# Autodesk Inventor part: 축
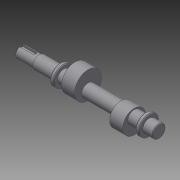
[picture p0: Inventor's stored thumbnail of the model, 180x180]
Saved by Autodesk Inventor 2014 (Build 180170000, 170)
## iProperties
Created: 2014-12
Part Number: 축
Material: 일반
Document SubType Name: Modeling
Designer: Owner
Density: 1 g/cm^3
Appearance: 기본값
Author: Owner
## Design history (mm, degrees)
sketch "스케치1"
  geometry: L1 (-90, 0)-(90, 0); L2 (-90, 0)-(-90, 7.5); L3 (-90, 7.5)-(-66, 7.5); L4 (-66, 7.5)-(-66, 8.5); L5 (-66, 8.5)-(-39, 8.5); L6 (-39, 8.5)-(-39, 13); L7 (-39, 13)-(-34, 13); L8 (-34, 13)-(-34, 8.5); L9 (-34, 8.5)-(72, 8.5); L10 (72, 13)-(72, 8.5); L11 (72, 13)-(77, 13); L12 (77, 13)-(77, 8.5); L13 (77, 8.5)-(90, 8.5); L14 (90, 8.5)-(90, 0); 2 further points
  constraints: 28 end point, 7 parallel, 6 perpendicular, 2 horizontal alignment, 1 coincident, 1 horizontal, 1 midpoint
  dimensions: "d0" = 180 distance of L1.start L1.end; "d1" = 15 diameter of L3 L1; "d2" = 17 diameter of L5 L1; "d3" = 26 diameter of L7 L1; "d4" = 5 distance between parallel lines of L8 L6; "d5" = 5 distance between parallel lines of L12 L10; "d6" = 26 diameter of L11 L1; "d7" = 24 distance between parallel lines of L4 L2; "d8" = 27 distance between parallel lines of L6 L4; "d9" = 13 distance between parallel lines of L14 L12
revolve "회전1" sketch "스케치1" stored, may be unused: angle "d10" = 90 deg
node "작업 평면1"
sketch "스케치2"
  geometry: C1 r 17.5 at (-6, 0); 1 further point
  constraints: 1 centre point, 1 horizontal alignment
  dimensions: "d12" = 35 diameter of C1; "d13" = 6 distance of point (0, 0) C1.centre
extrude "돌출1" join sketch "스케치2" distance "d14" = 17; taper "d15" = 0 deg
node "작업 평면2"
sketch "스케치3"
  geometry: C1 r 15 at (-5, 0); 1 further point
  constraints: 1 centre point, 1 horizontal alignment
  dimensions: "d17" = 30 diameter of C1; "d18" = 5 distance of C1.centre point (0, 0)
extrude "돌출2" join sketch "스케치3" distance "d19" = 17; taper "d20" = 0 deg
node "작업 평면3"
sketch "스케치4"
  geometry: L1 (-12, -7.5)-(-12, 7.5) reference; L2 (-12, 7.5)-(12, 7.5) reference; L3 (-12, -7.5)-(12, -7.5) reference; L4 (-12, 2.5)-(5.5, 2.5); L5 (5.5, -2.5)-(-12, -2.5); L6 (-12, -2.5)-(-12, 2.5); A1 r 2.5 centre (5.5, 0) between (5.5, -2.5) and (5.5, 2.5); 3 further points
  constraints: 6 end point, 2 midpoint, 2 parallel, 2 point on circle, 1 centre point, 1 coincident, 1 horizontal, 1 horizontal alignment, 1 point on line
  dimensions: "d21" = 5 distance between parallel lines of L5 L4; "d23" = 2.5 radius of A1; "d24" = 17.5 distance of L4.start L4.end
extrude "돌출3" cut sketch "스케치4" distance "d25" = 3; taper "d26" = 0 deg
chamfer "모따기1" distance "d27" = 1; stored, may be unused: second distance "d28" = 2, angle "d29" = 45 deg
chamfer "모따기2" distance "d30" = 1; stored, may be unused: second distance "d31" = 2, angle "d32" = 45 deg
chamfer "모따기3" distance "d33" = 1; stored, may be unused: second distance "d34" = 2, angle "d35" = 45 deg
chamfer "모따기4" distance "d36" = 1; stored, may be unused: second distance "d37" = 2, angle "d38" = 45 deg
node "솔리드1"
other parameters: "d11" = 14.5, "d16" = 14.5
